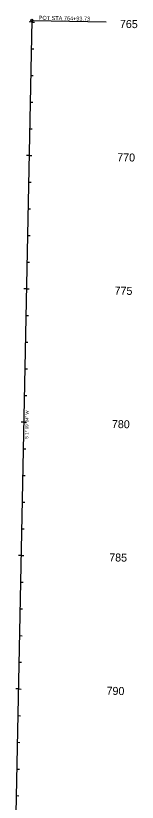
# Model space of a CAD drawing. Extents: x 2820825 to 2825694, y 116785 to 142398.
# Drawn here: x 2823700 to 2824157, y 139451 to 142398 of the extents above; entities that cross this region are included whole.
import ezdxf

# ---------------------------------------------------------------- set-up
doc = ezdxf.new("R2010")
doc.units = 0
for name, color, linetype in [('Roadway-Centerline main', 7, 'Continuous'), ('Roadway-Curve pc pt', 7, 'Continuous'), ('Text-Alignment info', 7, 'Continuous')]:
    doc.layers.add(name, color=color, linetype=linetype)

msp = doc.modelspace()

# ---------------------------------------------------------------- linework, layer by layer
at = {"layer": 'Roadway-Centerline main'}
for p, q in [((2823760.8, 142380.9), (2823701.1, 139408.5)), ((2823760.6, 142374.7), (2823750.6, 142374.9)), ((2823760.6, 142374.7), (2823770.6, 142374.5)), ((2823758.6, 142274.7), (2823768.6, 142274.5)), ((2823756.6, 142174.7), (2823766.6, 142174.5)), ((2823754.6, 142074.7), (2823764.6, 142074.5)), ((2823752.6, 141974.8), (2823762.6, 141974.6)), ((2823750.6, 141874.8), (2823740.6, 141875)), ((2823750.6, 141874.8), (2823760.6, 141874.6)), ((2823748.6, 141774.8), (2823758.6, 141774.6)), ((2823746.6, 141674.8), (2823756.6, 141674.6)), ((2823744.6, 141574.8), (2823754.6, 141574.6)), ((2823742.6, 141474.9), (2823752.6, 141474.7)), ((2823740.6, 141374.9), (2823730.6, 141375.1)), ((2823740.6, 141374.9), (2823750.6, 141374.7)), ((2823738.6, 141274.9), (2823748.5, 141274.7)), ((2823736.5, 141174.9), (2823746.5, 141174.7)), ((2823734.5, 141074.9), (2823744.5, 141074.7)), ((2823732.5, 140975), (2823742.5, 140974.8)), ((2823730.5, 140875), (2823720.5, 140875.2)), ((2823730.5, 140875), (2823740.5, 140874.8)), ((2823728.5, 140775), (2823738.5, 140774.8)), ((2823726.5, 140675), (2823736.5, 140674.8)), ((2823724.5, 140575), (2823734.5, 140574.8)), ((2823722.5, 140475.1), (2823732.5, 140474.9)), ((2823720.5, 140375.1), (2823710.5, 140375.3)), ((2823720.5, 140375.1), (2823730.5, 140374.9)), ((2823718.5, 140275.1), (2823728.5, 140274.9)), ((2823716.5, 140175.1), (2823726.5, 140174.9)), ((2823714.4, 140075.1), (2823724.4, 140074.9)), ((2823712.4, 139975.2), (2823722.4, 139975)), ((2823710.4, 139875.2), (2823700.4, 139875.4)), ((2823710.4, 139875.2), (2823720.4, 139875)), ((2823708.4, 139775.2), (2823718.4, 139775)), ((2823706.4, 139675.2), (2823716.4, 139675)), ((2823704.4, 139575.2), (2823714.4, 139575)), ((2823702.4, 139475.3), (2823712.4, 139475.1))]:
    msp.add_line(p, q, dxfattribs=at)
at = {"layer": 'Roadway-Curve pc pt'}
msp.add_line((2823764.8, 142380.9), (2824039.5, 142375.3), dxfattribs=at)
msp.add_circle((2823760.8, 142380.9), 4, dxfattribs=at)

# ---------------------------------------------------------------- texts
at = {"layer": 'Roadway-Centerline main'}
for s, p in [(' 765', (2824080.3, 142353.3)), (' 770', (2824070.2, 141853.4)), (' 775', (2824060.2, 141353.5)), (' 780', (2824050.2, 140853.6)), (' 785', (2824040.1, 140353.7)), (' 790', (2824030.1, 139853.8))]:
    msp.add_text(s, height=30, rotation=358.849, dxfattribs=at).set_placement(p)
at = {"layer": 'Roadway-Curve pc pt'}
msp.add_text('POT STA 764+93.73', height=15, rotation=358.849, dxfattribs=at).set_placement((2823786.8, 142383.4))
at = {"layer": 'Text-Alignment info'}
msp.add_text('S 1%%d 09\' 04" W', height=12, rotation=88.849, dxfattribs=at).set_placement((2823747.3, 140812.1))

doc.saveas('drawing.dxf')
